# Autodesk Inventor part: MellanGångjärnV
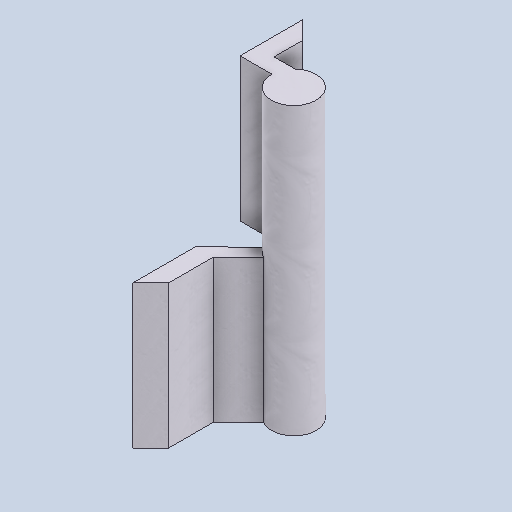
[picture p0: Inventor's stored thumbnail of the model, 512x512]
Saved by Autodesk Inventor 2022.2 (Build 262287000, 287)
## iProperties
Created: 2019-06
Part Number: MellanGångjärnV
Material: Aluminum 6061, Welded
Document SubType Name: Modeling
Designer: cl
Density: 2.7 g/cm^3
Appearance: Weld - Aluminum
Author: cl
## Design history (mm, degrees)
sketch "Sketch1"
  geometry: L1 (0, 0)-(0, -35); L2 (0, -35)-(-19.282, -53.9); L3 (-24.182, -48.901)-(-10, -35); L4 (-10, -35)-(-10, -10); L5 (-10, -10)-(0, 0); L6 (-19.282, -53.9)-(-24.182, -48.901); A1 r 12.5 centre (-30.302, -59.801) between (-24.182, -48.901) and (-19.282, -53.9)
  constraints: 12 end point, 3 point on circle, 2 parallel, 1 centre point, 1 perpendicular, 1 vertical
  dimensions: "d0" = 35 distance of L1.start L1.end; "d1" = 27 distance of L1.end L2.end; "d3" = 10 distance between parallel lines of L4 L1; "d4" = 135 deg angle of L1 L5; "d5" = 0 vertical distance of L3.end L1.end; "d6" = 25 diameter of A1; "d7" = 7 distance between parallel lines of L2 L3
extrude "Extrusion1" new body sketch "Sketch1" distance "d8" = 80; taper "d9" = 0 deg
sketch "Sketch2"
  geometry: L1 (10, 10)-(10, 35) reference; L2 (10, 35)-(24.182, 48.901) reference; L3 (19.282, 53.9)-(0, 35) reference; L4 (0, 35)-(0, 0) reference; L5 (0, 0)-(10, 10) reference; L6 (0, 60)-(0, 95); L7 (17.803, 60)-(0, 60); L8 (0, 95)-(10, 85); L9 (0, 95)-(14.142, 95); L10 (10, 85)-(10, 69); L11 (10, 69)-(21.839, 69); L12 (0, 35)-(0, 0) reference; A1 r 12.5 centre (30.302, 59.801) between (24.182, 48.901) and (19.282, 53.9) reference; A2 r 12.5 centre (30.302, 59.801) between (24.182, 48.901) and (19.282, 53.9) reference; A3 r 12.5 centre (30.302, 59.801) between (17.803, 60) and (21.839, 69)
  constraints: 12 end point, 4 point on circle, 2 vertical, 1 centre point, 1 coincident, 1 collinear, 1 equal length, 1 horizontal, 1 perpendicular
  dimensions: "d10" = 35 distance of L6.start L6.end; "d11" = 25 distance of L3.end L6.start; "d12" = 45 deg angle of L8 L9; "d13" = 10 distance between parallel lines of L6 L10; "d18" = 9 vertical distance of L11.end L7.start; "d19" = 9 distance from line of L10.end L7
extrude "Extrusion2" join sketch "Sketch2" distance "d20" = 80; taper "d21" = 0 deg
body "Solid1"
node "Projected Loop1"
